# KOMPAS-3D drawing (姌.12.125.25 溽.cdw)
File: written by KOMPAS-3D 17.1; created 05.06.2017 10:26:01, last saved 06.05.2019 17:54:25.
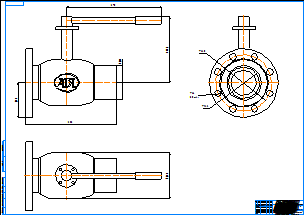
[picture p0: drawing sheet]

Sheet 1: A0, landscape

Title block, sheet 1: name: КШ.12.125.25 фс; material: Внимание! Данный продукт является объектом авторского права ООО «Торговый Дом АДЛ». / Запрещается изменение, копирование, распространение / (в том числе путем копирования на другие сайты и ресурсы в Интернете) / или любое иное использование информации и объектов без предварительного / согласия правообладателя (ООО «Торговый Дом АДЛ»).; sheets: 1; organisation: ООО "Торговый дом АДЛ"; sheet format: A0; stored path: C:\Users\kka\KOMPAS_Work\Модели кранов для исследований\Все краники\Редуцированный резьба-сварка ШК БИВАЛ\КШ.02.015.40 рс.cdw

Views: Вид 1, Проекционный вид 2, Проекционный вид 3
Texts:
  Klimkovich
  ADL
Dimensions and other numbers on the sheet: 258,4; 133; 370; 358; 135; 220; 123; 26; 8 Отв.; 180; 1:1; 1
